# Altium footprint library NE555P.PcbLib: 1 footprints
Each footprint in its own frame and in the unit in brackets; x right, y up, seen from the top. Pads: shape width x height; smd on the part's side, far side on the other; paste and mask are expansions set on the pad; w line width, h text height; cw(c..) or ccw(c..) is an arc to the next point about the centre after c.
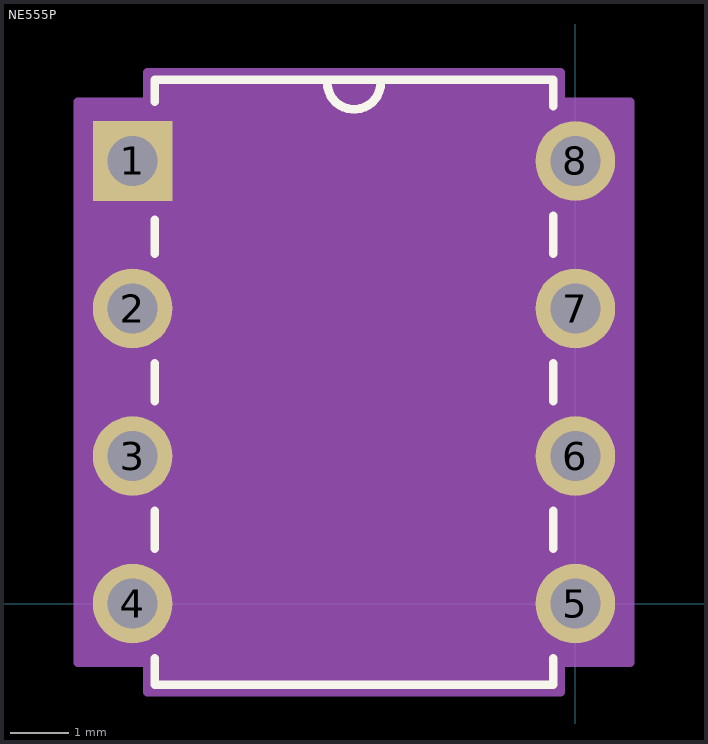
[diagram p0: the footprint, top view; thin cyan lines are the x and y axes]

## NE555P [mil]
pads (8):
  rect 54x54 / inner round 60 / far side rect 54x54 hole 34 paste+0 mask+0: 1(-300,300)
  round 54 / inner round 60 / far side round 54 hole 34 paste+0 mask+0: 2(-300,200) 3(-300,100) 4(-300,0) 5(0,0) 6(0,100) 7(0,200) 8(0,300)
Top Overlay:
  lines w6: -285,-37.19 -285,-55 -15,-55 -15,-37.19 ; -285,37.19 -285,62.81 ; -285,137.19 -285,162.81 ; -285,237.19 -285,259.9 ; -285,340.1 -285,355 -15,355 -15,337.19 ; -168.12,353.12 ccw(c-150,353.12) -131.88,353.12 ; -15,37.19 -15,62.81 ; -15,137.19 -15,162.81 ; -15,237.19 -15,262.81
Mechanical 13:
  lines w0: -162,350 ccw(c-150,350) -138,350
  lines w1: -317,-17 -280,-17 -280,17 -317,17 -317,-17 ; -317,83 -280,83 -280,117 -317,117 -317,83 ; -317,183 -280,183 -280,217 -317,217 -317,183 ; -317,283 -280,283 -280,317 -317,317 -317,283 ; -280,-50 -280,350 -20,350 -20,-50 -280,-50 ; -20,-17 17,-17 17,17 -20,17 -20,-17 ; -20,83 17,83 17,117 -20,117 -20,83 ; -20,183 17,183 17,217 -20,217 -20,183 ; -20,283 17,283 17,317 -20,317 -20,283
Mechanical 15:
  region: -10,-40 37,-40 37,340 -10,340 -10,360 -290,360 -290,340 -337,340 -337,-40 -290,-40 -290,-60 -10,-60
  lines w6: -337,-40 -290,-40 -290,-60 -10,-60 -10,-40 37,-40 37,340 -10,340 -10,360 -290,360 -290,340 -337,340 -337,-40
3D body "NE555P.step": height 210.12, standoff -90, extent -310,-50 10,350
3D body: height 10, standoff 0, extent 0,0 10,10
